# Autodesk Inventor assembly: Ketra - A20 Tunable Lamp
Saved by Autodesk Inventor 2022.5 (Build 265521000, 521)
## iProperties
Created: 2024-07
Part Number: Ketra - A20 Tunable Lamp
Document SubType Name: Assembly
Designer: AdminForWorker
Title: Ketra - A20 Tunable Lamp v4
Author: AdminForWorker
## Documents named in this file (2)
- z:\worker\convert-fusion-r03-cosv3\tmp\job-1\64\temp\files\890c6e9e-8bc5-494b-9aa5-545fa39bf4ab\Ketra - A20 Tunable Lamp v4.iam
- z:\worker\convert-fusion-r03-cosv3\tmp\job-1\64\temp\files\890c6e9e-8bc5-494b-9aa5-545fa39bf4ab\Ketra A20.ipt
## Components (1 placed, 1 different names)
1. Ketra A20:1
